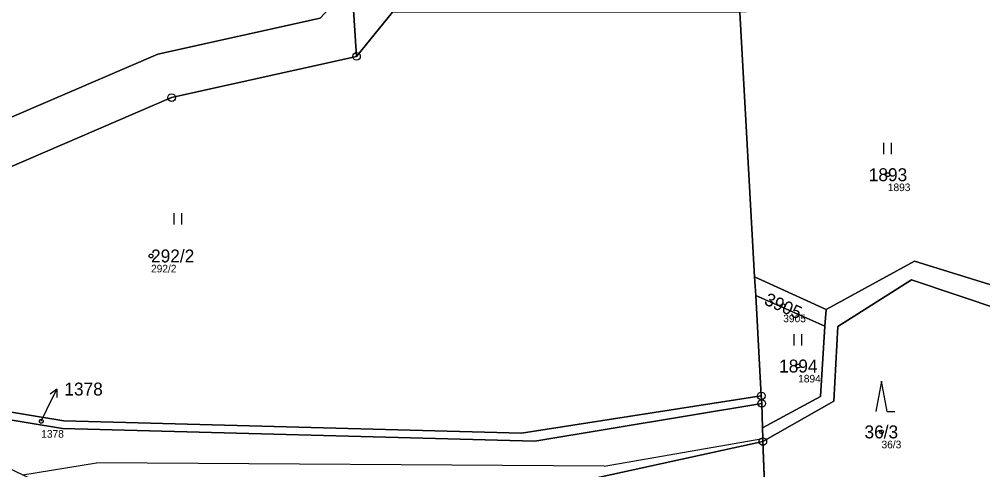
# Model space of a CAD drawing. Extents: x -658203 to -653176, y -1156738 to -1151709.
# Drawn here: x -654968.7 to -654841.9, y -1154357.6 to -1154298.3 of the extents above; entities that cross this region are included whole.
import ezdxf

# ---------------------------------------------------------------- set-up
doc = ezdxf.new("R2010")
doc.units = 0
for name, color, linetype in [('Vrstva 1', 7, 'Continuous'), ('Vrstva 2', 7, 'Continuous'), ('Vrstva 3', 7, 'Continuous'), ('Vrstva 4', 7, 'Continuous'), ('Vrstva 50', 7, 'Continuous'), ('Vrstva 51', 7, 'Continuous'), ('Vrstva 7', 7, 'Continuous'), ('Vrstva 8', 7, 'Continuous')]:
    doc.layers.add(name, color=color, linetype=linetype)

msp = doc.modelspace()

# ---------------------------------------------------------------- linework, layer by layer
at = {"layer": 'Vrstva 1'}
for p, q in [((-654924.27, -1154303.16), (-654924.89, -1154293.6)), ((-654919.54, -1154297.36), (-654924.27, -1154303.16)), ((-654871.88, -1154332.18), (-654873.84, -1154297.35)), ((-654871.74, -1154334.66), (-654871.88, -1154332.18)), ((-654871.88, -1154332.18), (-654862.48, -1154336.5)), ((-654871, -1154347.86), (-654871.74, -1154334.66)), ((-654862.62, -1154338.7), (-654871.74, -1154334.66)), ((-654862.62, -1154338.7), (-654862.48, -1154336.5)), ((-654871, -1154347.86), (-654870.94, -1154348.86)), ((-654870.85, -1154352.05), (-654870.94, -1154348.86)), ((-654870.81, -1154353.45), (-654870.85, -1154352.05)), ((-654870.8, -1154353.87), (-654870.81, -1154353.45)), ((-654870.8, -1154353.87), (-654870.26, -1154367.52))]:
    msp.add_line(p, q, dxfattribs=at)
for points in [[(-654924.89, -1154293.6), (-654929.06, -1154298.11), (-654950.44, -1154302.85), (-654984.12, -1154317.37), (-654991.11, -1154319.31)], [(-654924.27, -1154303.16), (-654948.6, -1154308.59), (-654982.12, -1154323.02)], [(-654862.48, -1154336.5), (-654850.86, -1154330.12), (-654830.88, -1154336.32)], [(-654832.43, -1154338.53), (-654833.49, -1154338.55), (-654851.22, -1154332.6), (-654860.94, -1154338.74), (-654861.45, -1154348.55), (-654870.8, -1154353.87)], [(-655043.2, -1154335.12), (-655038.72, -1154338.57), (-654962.79, -1154351.15)], [(-654870.94, -1154348.86), (-654900.79, -1154353.81), (-654962.95, -1154352.14), (-655042.43, -1154339.03)], [(-654870.85, -1154352.05), (-654863.22, -1154347.92), (-654862.62, -1154338.7)], [(-654962.79, -1154351.15), (-654902.54, -1154352.75), (-654871, -1154347.86)], [(-654962.23, -1154361.05), (-654900.12, -1154360.28), (-654870.8, -1154353.87)]]:
    msp.add_lwpolyline(points, dxfattribs=at)
at = {"layer": 'Vrstva 3'}
for p, q in [((-654854.86, -1154316.04), (-654854.86, -1154314.54)), ((-654853.86, -1154316.04), (-654853.86, -1154314.54)), ((-654948.26, -1154325.31), (-654948.26, -1154323.81)), ((-654947.26, -1154325.31), (-654947.26, -1154323.81)), ((-654866.66, -1154341.23), (-654866.66, -1154339.73)), ((-654865.66, -1154341.23), (-654865.66, -1154339.73)), ((-654855.18, -1154345.9), (-654855.93, -1154349.9)), ((-654854.43, -1154349.9), (-654855.18, -1154345.9)), ((-654854.43, -1154349.9), (-654853.43, -1154349.9))]:
    msp.add_line(p, q, dxfattribs=at)
at = {"layer": 'Vrstva 4'}
for p, q in [((-654891.68, -1154357.1), (-654870.81, -1154353.45)), ((-654968.2, -1154358.23), (-654958.48, -1154356.68)), ((-654891.68, -1154357.1), (-654958.48, -1154356.68))]:
    msp.add_line(p, q, dxfattribs=at)
at = {"layer": 'Vrstva 50'}
for centre in [(-654854.35, -1154318.74), (-654951.31, -1154329.44), (-654868.11, -1154336), (-654866.15, -1154343.93), (-654965.76, -1154351.2), (-654855.18, -1154352.6)]:
    msp.add_circle(centre, 0.25, dxfattribs=at)
at = {"layer": 'Vrstva 51'}
for points in [[(-654932.27, -1154211.02), (-654930.37, -1154227.71), (-654927.56, -1154252.45), (-654924.89, -1154293.6), (-654924.27, -1154303.16), (-654919.54, -1154297.36), (-654921.52, -1154255.33), (-654921.67, -1154252.21), (-654923.31, -1154246.35), (-654925.64, -1154227.91), (-654926.98, -1154218.04), (-654927.57, -1154208.07), (-654928.89, -1154195.89), (-654929.94, -1154185.97), (-654939.93, -1154185.43), (-654934.58, -1154190.75), (-654934, -1154195.82), (-654932.61, -1154208.04)], [(-654998.73, -1154248.76), (-654991.11, -1154319.31), (-654984.12, -1154317.37), (-654950.44, -1154302.85), (-654929.06, -1154298.11), (-654924.89, -1154293.6), (-654927.56, -1154252.45)], [(-654991.11, -1154319.31), (-655019.2, -1154327.08), (-655044.39, -1154329.21), (-655043.2, -1154335.12), (-655017.75, -1154332.95), (-654982.12, -1154323.02), (-654948.6, -1154308.59), (-654924.27, -1154303.16), (-654924.89, -1154293.6), (-654929.06, -1154298.11), (-654950.44, -1154302.85), (-654984.12, -1154317.37)], [(-654862.48, -1154336.5), (-654850.86, -1154330.12), (-654830.88, -1154336.32), (-654827.72, -1154295.44), (-654833.85, -1154295.31), (-654848.96, -1154296.08), (-654873.84, -1154297.35), (-654871.88, -1154332.18)], [(-655017.75, -1154332.95), (-655043.2, -1154335.12), (-655038.72, -1154338.57), (-654962.79, -1154351.15), (-654902.54, -1154352.75), (-654871, -1154347.86), (-654871.74, -1154334.66), (-654871.88, -1154332.18), (-654873.84, -1154297.35), (-654886.69, -1154297.35), (-654898.73, -1154297.36), (-654919.54, -1154297.36), (-654924.27, -1154303.16), (-654948.6, -1154308.59), (-654982.12, -1154323.02)], [(-654862.62, -1154338.7), (-654862.48, -1154336.5), (-654871.88, -1154332.18), (-654871.74, -1154334.66)], [(-654843.14, -1154366.95), (-654835.1, -1154369.71), (-654834.31, -1154360.78), (-654833.14, -1154347.51), (-654832.43, -1154338.53), (-654833.49, -1154338.55), (-654851.22, -1154332.6), (-654860.94, -1154338.74), (-654861.45, -1154348.55), (-654870.8, -1154353.87), (-654870.26, -1154367.52)], [(-654871.74, -1154334.66), (-654871, -1154347.86), (-654870.94, -1154348.86), (-654870.85, -1154352.05), (-654863.22, -1154347.92), (-654862.62, -1154338.7)], [(-655042.43, -1154339.03), (-654962.95, -1154352.14), (-654900.79, -1154353.81), (-654870.94, -1154348.86), (-654871, -1154347.86), (-654902.54, -1154352.75), (-654962.79, -1154351.15), (-655038.72, -1154338.57), (-655043.2, -1154335.12)], [(-654915.27, -1154373.44), (-654910.31, -1154372.79), (-654870.26, -1154367.52), (-654870.8, -1154353.87), (-654900.12, -1154360.28), (-654962.23, -1154361.05), (-654978.65, -1154366.48), (-654974.04, -1154373.53), (-654954.32, -1154374.66), (-654933.61, -1154375.85)]]:
    msp.add_lwpolyline(points, close=True, dxfattribs=at)
for points in [[(-655246.55, -1154309.75), (-655115.04, -1154331.4), (-655093.38, -1154334.97), (-655044.79, -1154342.97), (-655041.57, -1154343.4), (-654976.69, -1154354.21), (-654973.01, -1154355.95), (-654968.2, -1154358.23), (-654962.23, -1154361.05), (-654900.12, -1154360.28), (-654870.8, -1154353.87), (-654870.81, -1154353.45), (-654870.85, -1154352.05), (-654870.94, -1154348.86), (-654900.79, -1154353.81), (-654962.95, -1154352.14), (-655042.43, -1154339.03), (-655045.63, -1154338.55), (-655245.73, -1154305.55)], [(-654830.88, -1154336.32), (-654850.86, -1154330.12), (-654862.48, -1154336.5), (-654862.62, -1154338.7), (-654863.22, -1154347.92), (-654870.85, -1154352.05), (-654870.81, -1154353.45), (-654870.8, -1154353.87), (-654861.45, -1154348.55), (-654860.94, -1154338.74), (-654851.22, -1154332.6), (-654833.49, -1154338.55)]]:
    msp.add_lwpolyline(points, dxfattribs=at)
at = {"layer": 'Vrstva 7'}
for p, q in [((-654965.02, -1154349.66), (-654963.7, -1154346.96)), ((-654963.7, -1154346.96), (-654964.59, -1154347.64)), ((-654963.7, -1154346.96), (-654963.69, -1154348.08)), ((-654965.76, -1154351.2), (-654965.02, -1154349.66))]:
    msp.add_line(p, q, dxfattribs=at)
at = {"layer": 'Vrstva 8'}
for centre, radius in [((-654924.27, -1154303.16), 0.5), ((-654924.27, -1154303.16), 0.0303), ((-654948.6, -1154308.59), 0.5), ((-654948.6, -1154308.59), 0.0303), ((-654871, -1154347.86), 0.5), ((-654870.94, -1154348.86), 0.5), ((-654871, -1154347.86), 0.0303), ((-654870.94, -1154348.86), 0.0303), ((-654870.8, -1154353.87), 0.5), ((-654870.8, -1154353.87), 0.0303)]:
    msp.add_circle(centre, radius, dxfattribs=at)

# ---------------------------------------------------------------- texts
at = {"layer": 'Vrstva 2'}
for s, p in [('1893', (-654856.86, -1154319.59)), ('292/2', (-654951.31, -1154330.29)), ('1894', (-654868.66, -1154344.78)), ('1378', (-654962.72, -1154347.81)), ('36/3', (-654857.42, -1154353.45))]:
    msp.add_text(s, height=1.7, dxfattribs=at).set_placement(p)
msp.add_text('3905', height=1.7, rotation=336, dxfattribs=at).set_placement((-654870.75, -1154335.76))
at = {"layer": 'Vrstva 50'}
for s, p in [('1893', (-654854.35, -1154320.9)), ('292/2', (-654951.31, -1154331.6)), ('3905', (-654868.11, -1154338.16)), ('1894', (-654866.15, -1154346.09)), ('1378', (-654965.76, -1154353.36)), ('36/3', (-654855.18, -1154354.76))]:
    msp.add_text(s, height=1, dxfattribs=at).set_placement(p)

doc.saveas('drawing.dxf')
